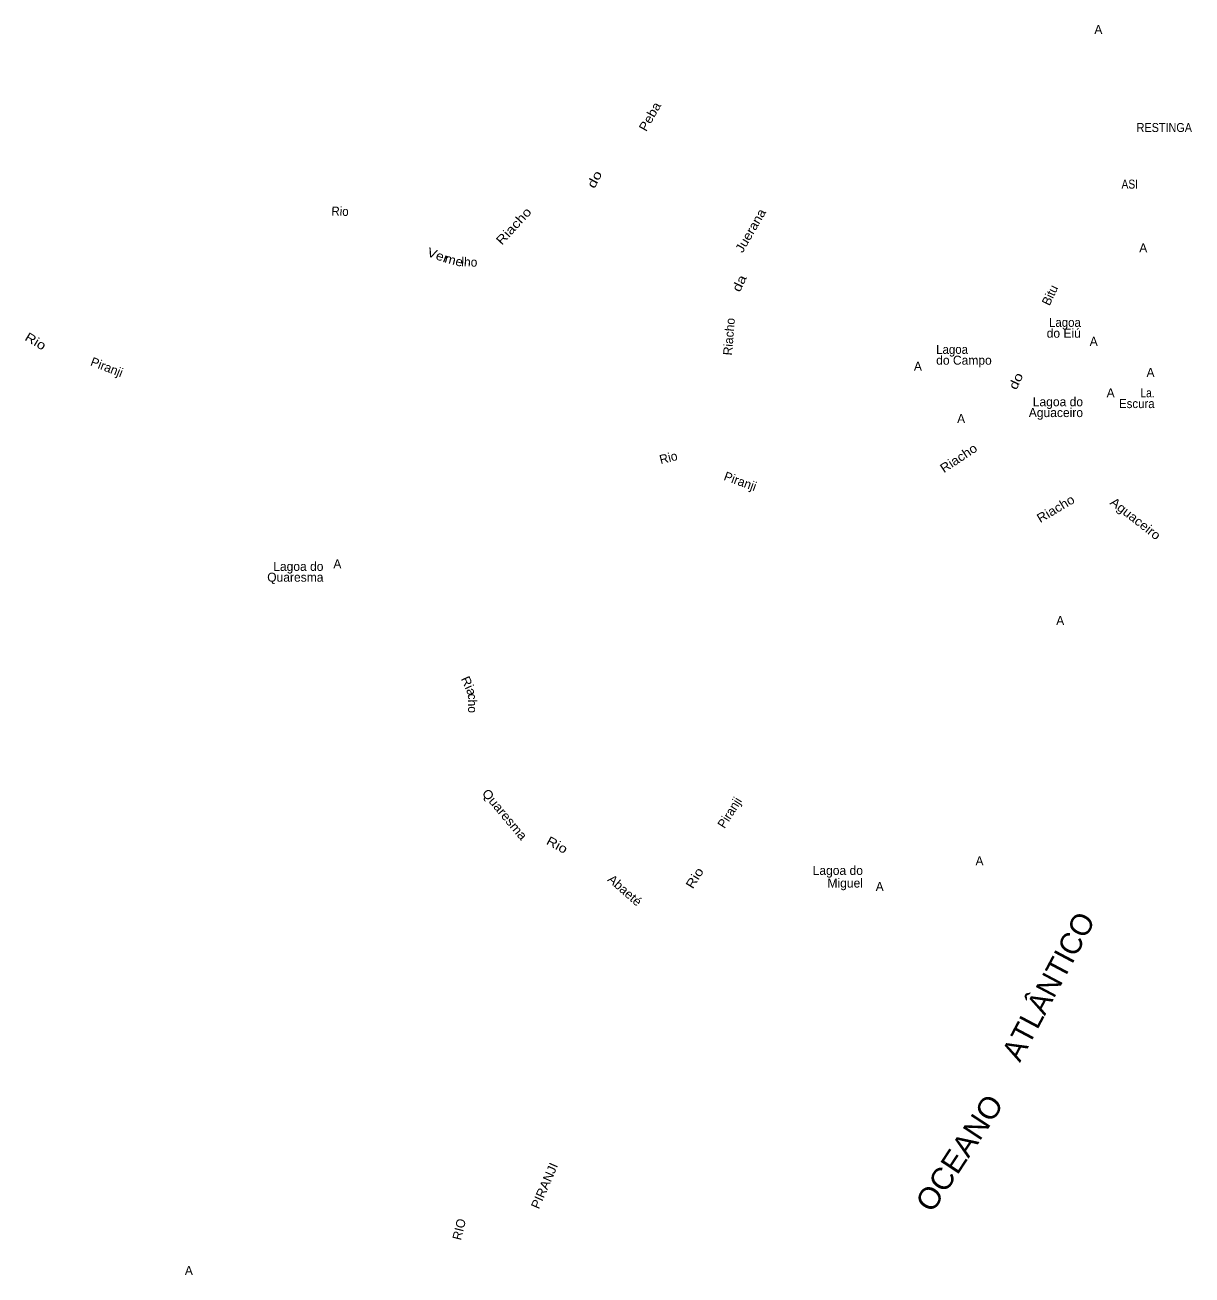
# Model space of a CAD drawing. Extents: x 649844 to 663669, y 8700676 to 8714511.
# Drawn here: x 657192 to 663669, y 8700676 to 8707613 of the extents above; entities that cross this region are included whole.
import ezdxf
from ezdxf.enums import TextEntityAlignment as Align

# ---------------------------------------------------------------- set-up
doc = ezdxf.new("R2010")
doc.units = 0
doc.header["$LTSCALE"] = 20
for name, color, linetype in [('20', 7, 'Continuous'), ('38', 7, 'Continuous'), ('51', 7, 'Continuous')]:
    doc.layers.add(name, color=color, linetype=linetype)

msp = doc.modelspace()

# ---------------------------------------------------------------- texts
at = {"layer": '20'}
for p in [(663149.51, 8707563.35), (663398.64, 8706351.79), (663123.71, 8705832.79), (663439.08, 8705659.79), (663217.63, 8705546.96), (662387.85, 8705404.03), (662937.74, 8704283.29), (662489.92, 8702949.37), (661935.87, 8702806.96), (658101.64, 8700676.13)]:
    msp.add_text('A', height=50, rotation=0.001, dxfattribs=at).set_placement(p, align=Align.CENTER)
for p in [(662125.76, 8705694.92), (658903.62, 8704597.71)]:
    msp.add_text('A', height=50, rotation=0.001, dxfattribs=at).set_placement(p)
at = {"layer": '38', "width": 0.9}
msp.add_text('RESTINGA', height=50, rotation=0.001, dxfattribs=at).set_placement((663515.53, 8707019.34), align=Align.CENTER)
at = {"layer": '38', "width": 0.85}
msp.add_text('ASI', height=50, rotation=0.001, dxfattribs=at).set_placement((663278.15, 8706705.31))
at = {"layer": '51'}
for s, rotation, width, p in [('Peba', 60.402, 1.1, (660682.17, 8707092.89)), ('do', 62.579, 1.3, (660375.07, 8706745.32)), ('Rio', 358.576, 0.95, (658940.28, 8706554.59)), ('Riacho', 47.464, 1.2, (659922.89, 8706480.65)), ('Juerana', 60.096, 1.1, (661240.78, 8706459.98)), ('Ver', 339.973, 1.15, (659475.57, 8706312.06)), ('me', 345.598, 1.1, (659567.07, 8706283.54)), ('da', 64.269, 1.25, (661179.19, 8706169.21)), ('Rio', 329.443, 1.2, (657238.38, 8705836.58)), ('do', 64.777, 1.25, (662714.21, 8705626.9)), ('Riacho', 33.648, 1.1, (662387.52, 8705188.94)), ('Riacho', 30.797, 1.1, (662925.13, 8704907.24)), ('Aguaceiro', 321.927, 1.1, (663340.03, 8704854.34)), ('Ria', 294.275, 1.1, (659632.93, 8703935.18)), ('Quaresma', 309.913, 1.1, (659835.54, 8703216.31)), ('Rio', 331.262, 1.2, (660133.5, 8703041.04)), ('Abaeté', 318.607, 1.05, (660505.17, 8702792.61)), ('Rio', 58.458, 1.2, (660930.08, 8702866.43)), ('PIRANJI', 66.338, 1.05, (660098.16, 8701161.64))]:
    msp.add_text(s, height=50, rotation=rotation, dxfattribs=dict(at, width=width)).set_placement(p, align=Align.CENTER)
for s, rotation, p in [('lho', 358.04, (659657.73, 8706273.32)), ('Bitu', 64.418, (662903.06, 8706103.59)), ('Riacho', 85.492, (661124.35, 8705882.08)), ('Piranji', 338.702, (657637.61, 8705691.57)), ('Rio', 14.13, (660769.34, 8705188.04)), ('Piranji', 340.083, (661153.74, 8705057.68)), ('cho', 270.855, (659651.07, 8703848.75)), ('Piranji', 57.804, (661123.95, 8703229.2)), ('RIO', 75.947, (659625.96, 8700923.91))]:
    msp.add_text(s, height=50, rotation=rotation, dxfattribs=at).set_placement(p, align=Align.CENTER)
for s, width, p in [('Lagoa', 0.95, (663052.3, 8705938.01)), ('La.', 0.85, (663461.86, 8705547.23)), ('Escura', 0.95, (663461.86, 8705487.23))]:
    msp.add_text(s, height=50, dxfattribs=dict(at, width=width)).set_placement(p, align=Align.RIGHT)
for s, p in [('do Eiú', (663052.3, 8705878.01)), ('Lagoa do', (663064.46, 8705497.45)), ('Aguaceiro', (663064.46, 8705437.45)), ('Lagoa do', (658848.74, 8704583.76)), ('Quaresma', (658848.74, 8704523.76)), ('Lagoa do', (661842.9, 8702896.5)), ('Miguel', (661842.9, 8702826.5))]:
    msp.add_text(s, height=50, dxfattribs=at).set_placement(p, align=Align.RIGHT)
at = {"layer": '51', "width": 0.95}
msp.add_text('Lagoa', height=50, dxfattribs=at).set_placement((662249.41, 8705788.09))
at = {"layer": '51'}
msp.add_text('do Campo', height=50, dxfattribs=at).set_placement((662249.41, 8705728.09))
msp.add_text(' ATLÂNTICO', height=120, rotation=62.057, dxfattribs=at).set_placement((663136.28, 8702647.66), align=Align.RIGHT)
at = {"layer": '51', "width": 1.05}
msp.add_text('OCEANO', height=120, rotation=56.617, dxfattribs=at).set_placement((662629.13, 8701625.52), align=Align.RIGHT)

doc.saveas('drawing.dxf')
